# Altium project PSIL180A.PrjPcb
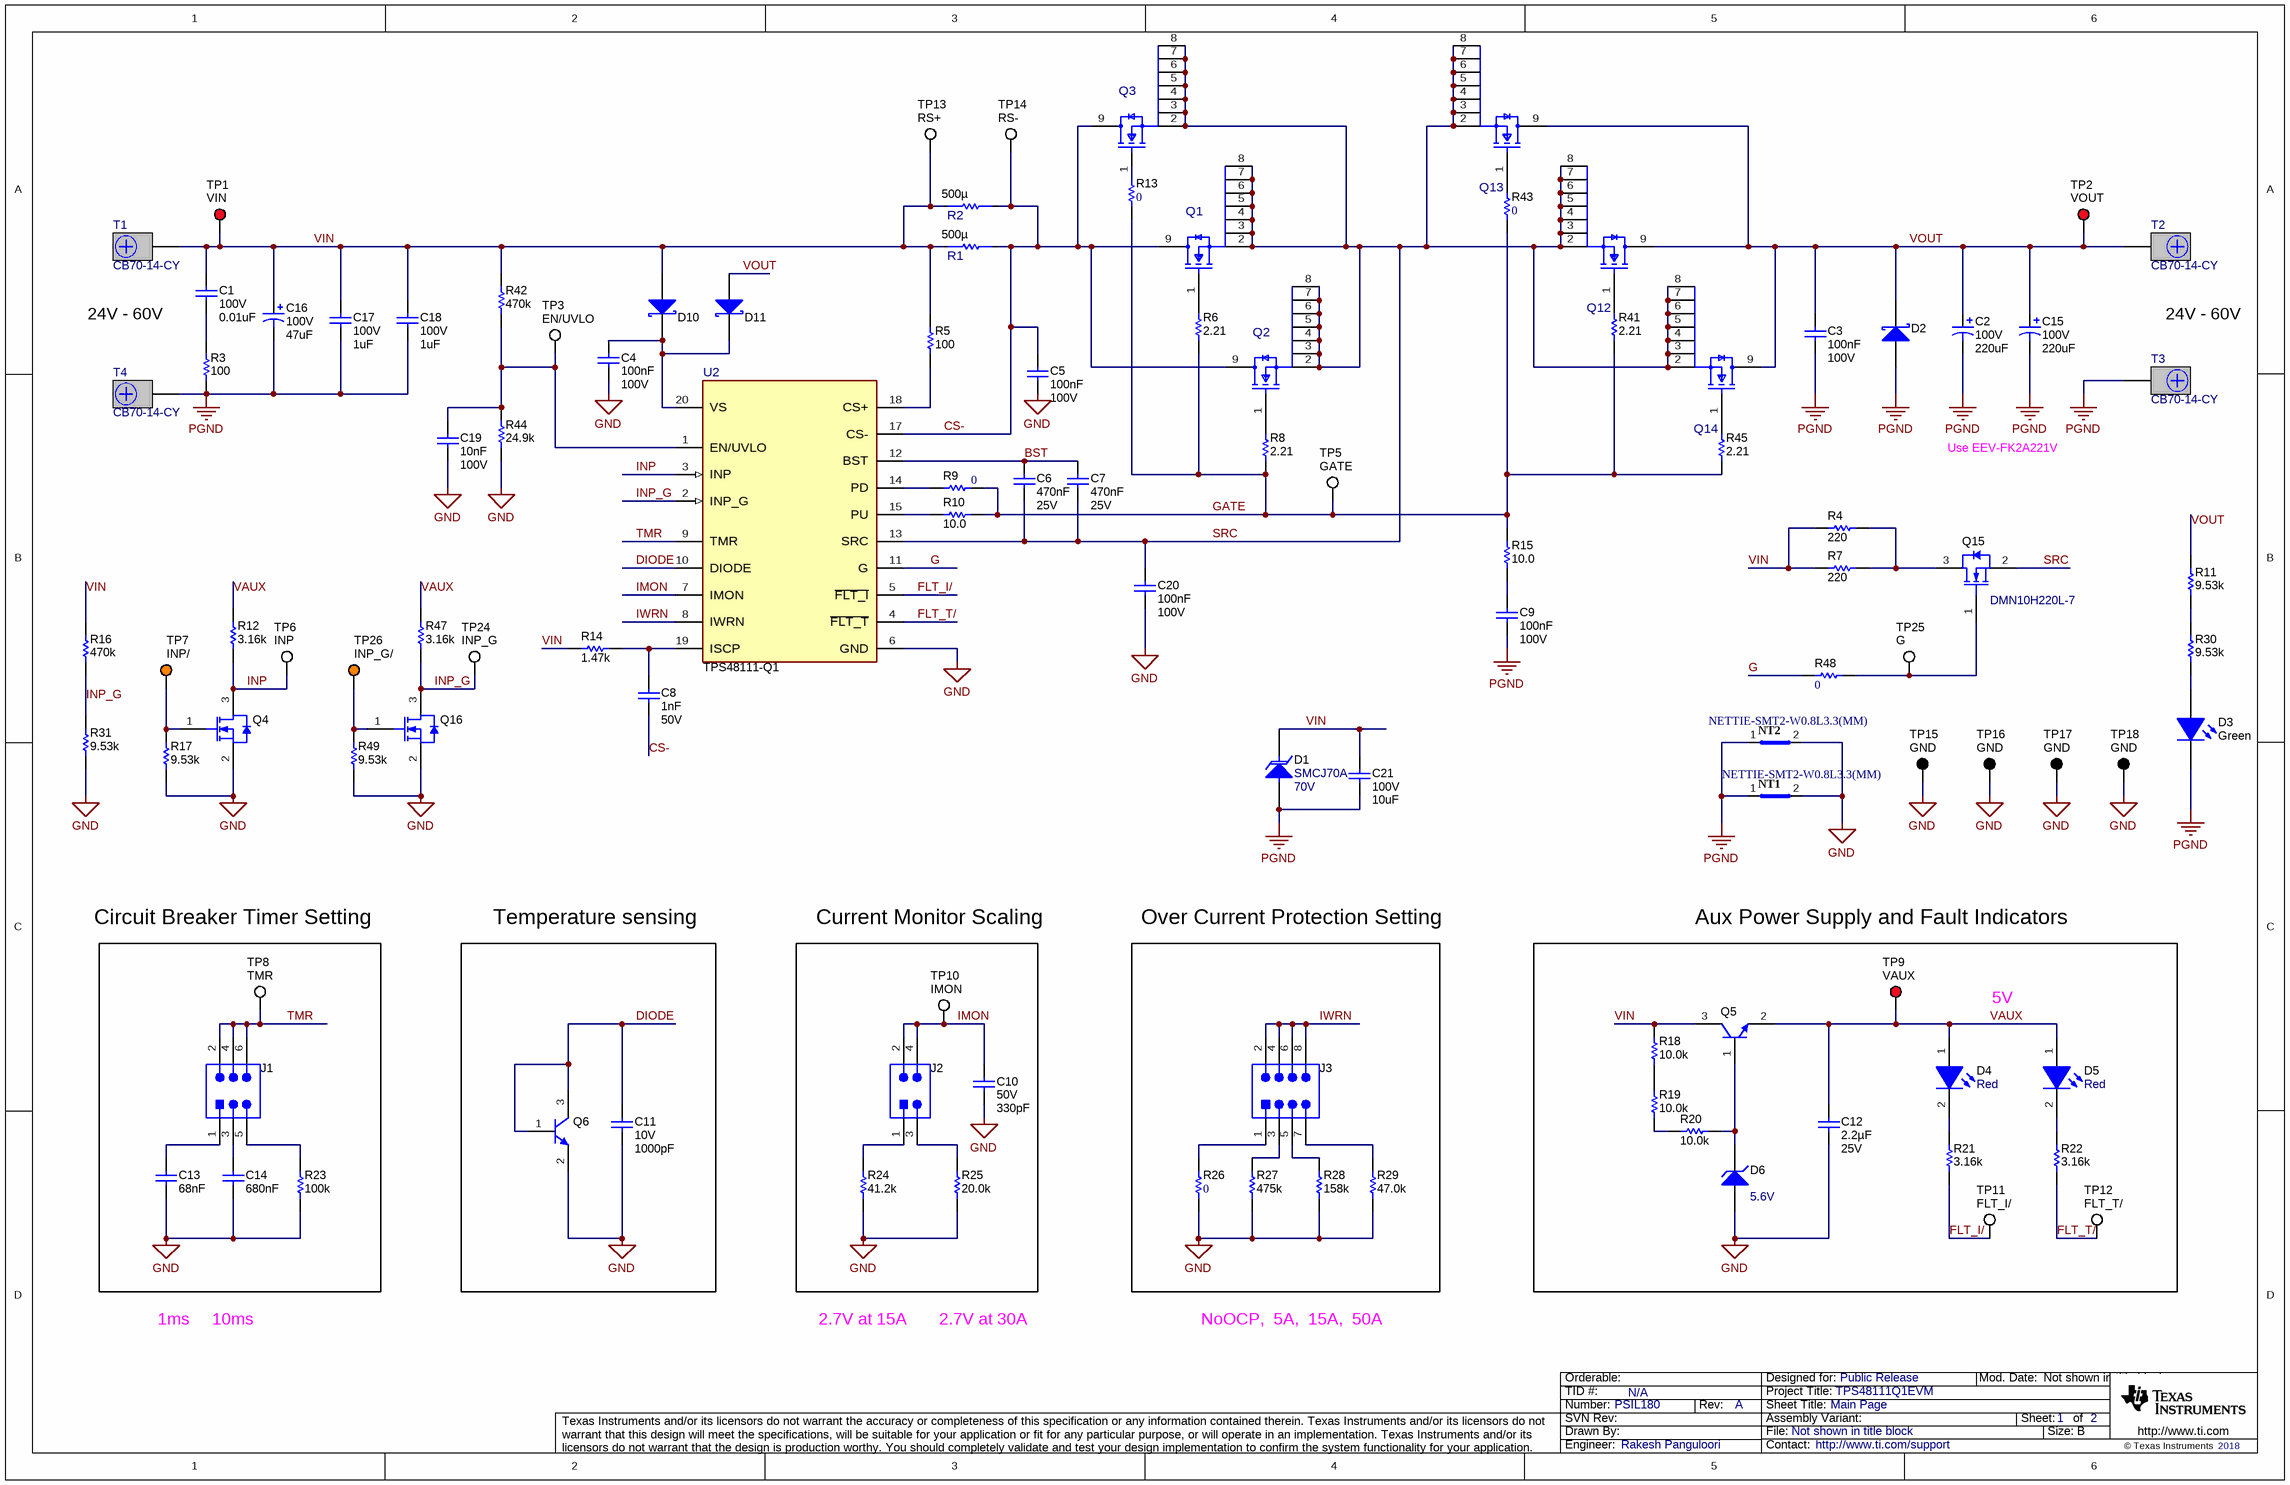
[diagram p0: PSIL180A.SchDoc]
TID: N/A; TechSupport: http://www.ti.com/support; SCH_Rev: A; PRJ_Title: TPS48111Q1EVM; PRJ_Number: PSIL180; PRJ_Engineer: Rakesh Panguloori; PRJ_Customer: Public Release; PCB_Rev: A; CopyrightYear: 2018
2 sheets, 135 parts. Net scope: global (net labels, ports and power ports of the same name join across sheets).
Board file: PSIL180A.PcbDoc
Sheets:
  PSIL180A.SchDoc
  PSIL180A_Hardware.SchDoc

## Sheet PSIL180A.SchDoc: Main Page
size 431 x 279 mm; Date: Not shown in title block; ApprovedBy: Not shown in title block; CheckedBy: Not shown in title block; Author: Not shown in title block; CompanyName: Not shown in title block; Engineer: Not shown in title block; Organization: Not shown in title block; Address1: Not shown in title block; Address2: Not shown in title block; Address3: Not shown in title block; Address4: Not shown in title block; DocumentNumber: 1; Revision: Use project parameter SCH_Rev; SheetNumber: 1; SheetTotal: 2; PageSetup: Record=PageOptions¦CenterHorizontal=True¦CenterVertical=True¦PrintScale=1.00¦XCorrection=1.00¦YCorrection=1.00¦PrintKind=0¦BorderSize=5000000¦LeftOffset=0¦BottomOffset=0¦Orientation=2¦PaperLength=1000¦PaperWidth=1000¦Scale=100¦PaperSource=15¦PrintQuality=600¦MediaType=1¦DitherType=10¦PaperKind=Letter¦PrintScaleMode=1

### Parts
C1  VDC_V: 100V  ValueDisplayed: 0.01uF  [1206]  (hidden comment: 12061C103KAT2A)
C2  VDC_V: 100V  ValueDisplayed: 220uF  [SM_RADIAL_K16]  (hidden comment: EEV-FK2A221M)
C3  Cap_F: 100nF  VDC_V: 100V  [0805_HV]  (hidden comment: CGA4J2X7R2A104K125AA)
C4  Cap_F: 100nF  VDC_V: 100V  [0805_HV]  (hidden comment: CGA4J2X7R2A104K125AA)
C5  Cap_F: 100nF  VDC_V: 100V  [0805_HV]  (hidden comment: CGA4J2X7R2A104K125AA)
C6  Cap_F: 470nF  VDC_V: 25V  [0603]  (hidden comment: CGA3E3X7R1E474K080AB)
C7  Cap_F: 470nF  VDC_V: 25V  [0603]  (hidden comment: CGA3E3X7R1E474K080AB)
C8  Cap_F: 1nF  VDC_V: 50V  [0805_HV]  (hidden comment: C0805C102J5RACTU)
C9  Cap_F: 100nF  VDC_V: 100V  [0805_HV]  (hidden comment: CGA4J2X7R2A104K125AA)
C10  VDC_V: 50V  ValueDisplayed: 330pF  [0402]  (hidden comment: GRM155R71H331KA01D)
C11  VDC_V: 10V  ValueDisplayed: 1000pF  [0402]  (hidden comment: 0402ZC102KAT2A)
C12  Cap_F: 2.2µF  VDC_V: 25V  [0805_HV]  (hidden comment: GCM21BR71E225KA73L)
C13  Cap_F: 68nF  [0805_HV]  (hidden comment: C0805C683K1RACTU)
C14  Cap_F: 680nF  [0805_HV]  (hidden comment: C0805C684K5RACTU)
C15  VDC_V: 100V  ValueDisplayed: 220uF  [SM_RADIAL_K16]  (hidden comment: EEV-FK2A221M)
C16  VDC_V: 100V  ValueDisplayed: 47uF  [SM_RADIAL_H13]  (hidden comment: EEV-FK2A470Q)
C17  VDC_V: 100V  ValueDisplayed: 1uF  [1812_254]  (hidden comment: C4532X7R2A105K230KA)
C18  VDC_V: 100V  ValueDisplayed: 1uF  [1812_254]  (hidden comment: C4532X7R2A105K230KA)
C19  Cap_F: 10nF  VDC_V: 100V  [0805_HV]  (hidden comment: 08051C103JAT2A)
C20  Cap_F: 100nF  VDC_V: 100V  [0805_HV]  (hidden comment: CGA4J2X7R2A104K125AA)
C21  VDC_V: 100V  ValueDisplayed: 10uF  [2220_280]  (hidden comment: 22201C106MAT2A)
D1  SMCJ70A  value 70V  [SMC_265]
D2  SS2H10-E3/5BT  [SMB]  (value not drawn)
D3  value Green  [LTST-C170KGKT_Green]  (hidden comment: LTST-C170KGKT)
D4  value Red  [LED_LTST-C170_Red]  (hidden comment: LTST-C170KRKT)
D5  value Red  [LED_LTST-C170_Red]  (hidden comment: LTST-C170KRKT)
D6  value 5.6V  [SOD-323]  (hidden comment: SZMM3Z5V6ST1G)
D10  BAT46WH,115  [SOD-123F]  (value not drawn)
D11  BAT46WH,115  [SOD-123F]  (value not drawn)
J1  PEC03DAAN  [SULLINS_PEC03DAAN]  (value not drawn)
J2  PEC02DAAN  [Sullins_PEC02DAAN]  (value not drawn)
J3  PEC04DAAN  [CONN_PEC04DAAN]  (value not drawn)
NT1  NETTIE-SMT2-W0.8L3.3(MM)  [NETTIE-SMT2-W0.8L3.3(MM)]  (net tie, no BOM)
NT2  NETTIE-SMT2-W0.8L3.3(MM)  [NETTIE-SMT2-W0.8L3.3(MM)]  (net tie, no BOM)
Q1  IAUS300N08S5N012ATMA1  [FP-IAUS300N08S5N012ATMA1_HSOG-8-MFG]  (value not drawn)
Q2  IAUS300N08S5N012ATMA1  [FP-IAUS300N08S5N012ATMA1_HSOG-8-MFG]  (value not drawn)
Q3  IAUS300N08S5N012ATMA1  [FP-IAUS300N08S5N012ATMA1_HSOG-8-MFG]  (value not drawn)
Q4  2N7002W-7-F  [SOT-323]  (value not drawn)
Q5  PMBT5551,215  [SOT-23]  (value not drawn)
Q6  MMBT3904  [SOT-23]  (value not drawn)
Q12  IAUS300N08S5N012ATMA1  [FP-IAUS300N08S5N012ATMA1_HSOG-8-MFG]  (value not drawn)
Q13  IAUS300N08S5N012ATMA1  [FP-IAUS300N08S5N012ATMA1_HSOG-8-MFG]  (value not drawn)
Q14  IAUS300N08S5N012ATMA1  [FP-IAUS300N08S5N012ATMA1_HSOG-8-MFG]  (value not drawn)
Q15  DMN10H220L-7  [SOT-23]
Q16  2N7002W-7-F  [SOT-323]  (value not drawn)
R1  Res_ohm: 500µ  [FP-WSL3921L5000FEA_3921-MFG]  (hidden comment: WSL3921L5000FEA)
R2  Res_ohm: 500µ  [FP-WSL3921L5000FEA_3921-MFG]  (hidden comment: WSL3921L5000FEA)
R3  ValueDisplayed: 100  [1206]  (hidden comment: CRCW1206100RFKEAHP)
R4  ValueDisplayed: 220  [2512]  (hidden comment: CRCW2512220RFKEG)
R5  ValueDisplayed: 100  [0805_HV]  (hidden comment: CRCW0805100RFKEA)
R6  ValueDisplayed: 2.21  [0603]  (hidden comment: RC0603FR-072R21L)
R7  ValueDisplayed: 220  [2512]  (hidden comment: CRCW2512220RFKEG)
R8  ValueDisplayed: 2.21  [0603]  (hidden comment: RC0603FR-072R21L)
R9  ValueDisplayed: 0  [0603]  (hidden comment: CRCW06030000Z0EA)
R10  ValueDisplayed: 10.0  [0603]  (hidden comment: CRCW060310R0FKEAHP)
R11  ValueDisplayed: 9.53k  [0603]  (hidden comment: RC0603FR-079K53L)
R12  ValueDisplayed: 3.16k  [0603]  (hidden comment: CRCW06033K16FKEA)
R13  ValueDisplayed: 0  [0603]  (hidden comment: CRCW06030000Z0EA)
R14  ValueDisplayed: 1.47k  [0603]  (hidden comment: RT0603BRD071K47L)
R15  ValueDisplayed: 10.0  [0805_HV]  (hidden comment: RC0805FR-0710RL)
R16  ValueDisplayed: 470k  [0603]  (hidden comment: RC0603FR-07470KL)
R17  ValueDisplayed: 9.53k  [0603]  (hidden comment: RC0603FR-079K53L)
R18  ValueDisplayed: 10.0k  [0805_HV]  (hidden comment: ERJ-6ENF1002V)
R19  ValueDisplayed: 10.0k  [0805_HV]  (hidden comment: ERJ-6ENF1002V)
R20  ValueDisplayed: 10.0k  [0805_HV]  (hidden comment: ERJ-6ENF1002V)
R21  ValueDisplayed: 3.16k  [0603]  (hidden comment: CRCW06033K16FKEA)
R22  ValueDisplayed: 3.16k  [0603]  (hidden comment: CRCW06033K16FKEA)
R23  ValueDisplayed: 100k  [0603]  (hidden comment: CRCW0603100KFKEA)
R24  ValueDisplayed: 41.2k  [0603]  (hidden comment: RC0603FR-0741K2L)
R25  ValueDisplayed: 20.0k  [0603]  (hidden comment: RT0603DRE0720KL)
R26  ValueDisplayed: 0  [0603]  (hidden comment: ERJ-3GEY0R00V)
R27  ValueDisplayed: 475k  [0603]  (hidden comment: RC0603FR-07475KL)
R28  ValueDisplayed: 158k  [0603]  (hidden comment: CRCW0603158KFKEA)
R29  ValueDisplayed: 47.0k  [0603]  (hidden comment: CRCW060347K0FKEA)
R30  ValueDisplayed: 9.53k  [0603]  (hidden comment: RC0603FR-079K53L)
R31  ValueDisplayed: 9.53k  [0603]  (hidden comment: RC0603FR-079K53L)
R41  ValueDisplayed: 2.21  [0603]  (hidden comment: RC0603FR-072R21L)
R42  ValueDisplayed: 470k  [0603]  (hidden comment: RC0603FR-07470KL)
R43  ValueDisplayed: 0  [0603]  (hidden comment: CRCW06030000Z0EA)
R44  ValueDisplayed: 24.9k  [0805_HV]  (hidden comment: CRCW080524K9FKEA)
R45  ValueDisplayed: 2.21  [0603]  (hidden comment: RC0603FR-072R21L)
R47  ValueDisplayed: 3.16k  [0603]  (hidden comment: CRCW06033K16FKEA)
R48  ValueDisplayed: 0  [0603]  (hidden comment: ERJ-3GEY0R00V)
R49  ValueDisplayed: 9.53k  [0603]  (hidden comment: RC0603FR-079K53L)
T1  CB70-14-CY  [CB70-14-CY]
T2  CB70-14-CY  [CB70-14-CY]
T3  CB70-14-CY  [CB70-14-CY]
T4  CB70-14-CY  [CB70-14-CY]
TP1  VIN  [Keystone5010]
TP2  VOUT  [Keystone5010]
TP3  EN/UVLO  [Keystone5012]
TP5  GATE  [Keystone5012]
TP6  INP  [Keystone5012]
TP7  INP/  [Keystone5013]
TP8  TMR  [Keystone5012]
TP9  VAUX  [Keystone5010]
TP10  IMON  [Keystone5012]
TP11  FLT_I/  [Keystone5012]
TP12  FLT_T/  [Keystone5012]
TP13  RS+  [Keystone5012]
TP14  RS-  [Keystone5012]
TP15  GND  [Keystone5011]
TP16  GND  [Keystone5011]
TP17  GND  [Keystone5011]
TP18  GND  [Keystone5011]
TP24  INP_G  [Keystone5012]
TP25  G  [Keystone5012]
TP26  INP_G/  [Keystone5013]
U2  PartNumber: TPS48111-Q1  [0-MFG]  (hidden comment: PTPS48111-Q1)

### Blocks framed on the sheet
5V: C12 D4-D6 Q5 R18-R22 TP9 TP11 TP12

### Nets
GND: C4.2 C5.2 C10.2 C11.2 C12.2 C13.2 C14.2 C19.2 C20.2 D6.2(A) NT1.2(Net2) NT2.2(Net2) Q4.2(S) Q6.2(E) Q16.2(S) R17.1 R23.1 R24.1 R25.1 R26.2 R27.1 R28.1 R29.1 R31.1 R44.1 R49.1 TP15.1 TP16.1 TP17.1 TP18.1 U2.6(GND)
PGND: C2.2(-) C3.2 C9.2 C15.2(-) C16.2(-) C17.2 C18.2 C21.2 D1.2(A) D2.2(A) D3.2(K) NT1.1(Net1) NT2.1(Net1) R3.1 T3.1 T4.1
BST: C6.1 C7.1 U2.12(BST)
CS-: C5.1 C8.2 Q1.9(DRAIN) Q2.9(DRAIN) Q3.9(DRAIN) R1.2 R2.2 TP14.1 U2.17(CS-)
DIODE: C11.1 Q6.1(B) Q6.3(C) U2.10(DIODE)
FLT_I/: R21.1 TP11.1 U2.5(~{FLT_I})
FLT_T/: R22.1 TP12.1 U2.4(~{FLT_T})
G: R48.2 U2.11(G)
GATE: R6.1 R8.1 R9.2 R10.2 R13.1 R15.2 R41.1 R43.1 R45.1 TP5.1
IMON: C10.1 J2.2 J2.4 TP10.1 U2.7(IMON)
INP: Q4.3(D) R12.1 TP6.1 U2.3(INP)
INP_G: Q16.3(D) R16.1 R31.2 R47.1 TP24.1 U2.2(INP_G)
IWRN: J3.2 J3.4 J3.6 J3.8 U2.8(IWRN)
SRC: C6.2 C7.2 C20.1 Q1.2(SOURCE) Q1.3(SOURCE) Q1.4(SOURCE) Q1.5(SOURCE) Q1.6(SOURCE) Q1.7(SOURCE) Q1.8(SOURCE) Q2.2(SOURCE) Q2.3(SOURCE) Q2.4(SOURCE) Q2.5(SOURCE) Q2.6(SOURCE) Q2.7(SOURCE) Q2.8(SOURCE) Q3.2(SOURCE) Q3.3(SOURCE) Q3.4(SOURCE) Q3.5(SOURCE) Q3.6(SOURCE) Q3.7(SOURCE) Q3.8(SOURCE) Q12.2(SOURCE) Q12.3(SOURCE) Q12.4(SOURCE) Q12.5(SOURCE) Q12.6(SOURCE) Q12.7(SOURCE) Q12.8(SOURCE) Q13.2(SOURCE) Q13.3(SOURCE) Q13.4(SOURCE) Q13.5(SOURCE) Q13.6(SOURCE) Q13.7(SOURCE) Q13.8(SOURCE) Q14.2(SOURCE) Q14.3(SOURCE) Q14.4(SOURCE) Q14.5(SOURCE) Q14.6(SOURCE) Q14.7(SOURCE) Q14.8(SOURCE) Q15.2(S) U2.13(SRC)
TMR: J1.2 J1.4 J1.6 TP8.1 U2.9(TMR)
VAUX: C12.1 D4.1(A) D5.1(A) Q5.2(E) R12.2 R47.2 TP9.1
VIN: C1.1 C16.1(+) C17.1 C18.1 C21.1 D1.1(K) D10.2(A) Q5.3(C) R1.1 R2.1 R4.1 R5.2 R7.1 R14.1 R16.2 R18.2 R42.2 T1.1 TP1.1 TP13.1
VOUT: C2.1(+) C3.1 C15.1(+) D2.1(K) D11.2(A) Q12.9(DRAIN) Q13.9(DRAIN) Q14.9(DRAIN) R11.2 T2.1 TP2.1
NetC1_2: C1.2 R3.2
NetC4_1: C4.1 D10.1(K) D11.1(K) U2.20(VS)
NetC8_1: C8.1 R14.2 U2.19(ISCP)
NetC9_1: C9.1 R15.1
NetC13_1: C13.1 J1.1
NetC14_1: C14.1 J1.3
NetC19_1: C19.1 R42.1 R44.2 TP3.1 U2.1(EN/UVLO)
NetD3_1: D3.1(A) R30.1
NetD4_2: D4.2(K) R21.2
NetD5_2: D5.2(K) R22.2
NetD6_1: D6.1(K) Q5.1(B) R20.1
NetJ1_5: J1.5 R23.2
NetJ2_1: J2.1 R24.2
NetJ2_3: J2.3 R25.2
NetJ3_1: J3.1 R26.1
NetJ3_3: J3.3 R27.2
NetJ3_5: J3.5 R28.2
NetJ3_7: J3.7 R29.2
NetQ1_1: Q1.1(GATE) R6.2
NetQ2_1: Q2.1(GATE) R8.2
NetQ3_1: Q3.1(GATE) R13.2
NetQ4_1: Q4.1(G) R17.2 TP7.1
NetQ12_1: Q12.1(GATE) R41.2
NetQ13_1: Q13.1(GATE) R43.2
NetQ14_1: Q14.1(GATE) R45.2
NetQ15_1: Q15.1(G) R48.1 TP25.1
NetQ15_3: Q15.3(D) R4.2 R7.2
NetQ16_1: Q16.1(G) R49.2 TP26.1
NetR5_1: R5.1 U2.18(CS+)
NetR9_1: R9.1 U2.14(PD)
NetR10_1: R10.1 U2.15(PU)
NetR11_1: R11.1 R30.2
NetR18_1: R18.1 R19.2
NetR19_1: R19.1 R20.2

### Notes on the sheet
- 24V - 60V
- Use EEV-FK2A221V
- Circuit Breaker Timer Setting
- Temperature sensing
- Current Monitor Scaling
- Over Current Protection Setting
- Aux Power Supply and Fault Indicators
- 1ms     10ms
- 2.7V at 15A
- 2.7V at 30A
- NoOCP,  5A,  15A,  50A

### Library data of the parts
C1 = CMP-0008485-2: CAP, CERM, 0.01 uF, 100 V, +/- 10%, X7R, 1206; Manufacturer: AVX; TaMin_C: -55°C; ESR_ohm: 0.119; Polarized: N; SizeAreaWB_mm2: 10.92; Value1: 0.119 ohm; U/M: EA; Value: 0.01uF; TaMax_C: 125°C; SizeZ_mm: 1.35; SizeX_mm: 3.2; SizeY_mm: 1.6; SizeArea_mm2: 5.12; Cap_F: 10nF; AEC Category: Q200
C2 C15 = CMP-0011223-2: CAP, AL, 220 uF, 100 V, +/- 20%, 0.153 ohm, AEC-Q200 Grade 2, SMD; Manufacturer: Panasonic; TaMin_C: -55°C; ESR_ohm: 0.153; Polarized: Y; SizeAreaWB_mm2: 483; U/M: EA; Value: 220uF; TaMax_C: 105°C; SizeZ_mm: 16.5; SizeX_mm: 21; SizeY_mm: 19; Cap_Case: K16; SizeArea_mm2: 399; CompType: Capacitor; Cap_F: 220µF; IRMS_A: 917mA; AEC Grade: 2; AEC Category: Q200
C3-C5 C9 C20 = CMP-0007969-2: CAP, CERM, 0.1 uF, 100 V, +/- 10%, X7R, AEC-Q200 Grade 1, 0805; Manufacturer: TDK; TaMin_C: -55°C; ESR_ohm: 0.020726; Polarized: N; SizeAreaWB_mm2: 6.75; Value1: 0.020726 ohm; U/M: EA; Value: 0.1uF; TaMax_C: 125°C; SizeZ_mm: 1.45; SizeX_mm: 2; SizeY_mm: 1.25; Cap_Case: 0805; SizeArea_mm2: 2.5; AEC Qualified: Y; IRMS_A: 1.456A; AEC Grade: 1; AEC Category: Q200
C6 C7 = CMP-0007092-5: CAP, CERM, 0.47 uF, 25 V, +/- 10%, X7R, AEC-Q200 Grade 1, 0603; Manufacturer: TDK; TaMin_C: -55°C; Polarized: N; SizeAreaWB_mm2: 4.68; Value1: Unknown; U/M: EA; Value: 0.47uF; TaMax_C: 125°C; SizeZ_mm: 1; SizeX_mm: 1.6; SizeY_mm: 0.8; SizeArea_mm2: 1.28; AEC Qualified: Y; AEC Category: Q200
C8 = CMP-0007711-2: CAP, CERM, 1000 pF, 50 V, +/- 5%, X7R, 0805; Manufacturer: Kemet; TaMin_C: -55°C; ESR_ohm: 0.384; Polarized: N; SizeAreaWB_mm2: 6.75; Value1: 0.384 ohm; U/M: EA; Value: 1000pF; TaMax_C: 125°C; SizeZ_mm: 1.45; SizeX_mm: 2; SizeY_mm: 1.25; Cap_Case: 0805; SizeArea_mm2: 2.5; IRMS_A: 214mA; AEC Category: Q200
C10 = CMP-0006687-2: CAP, CERM, 330 pF, 50 V, +/- 10%, X7R, 0402; Manufacturer: MuRata; TaMin_C: -55°C; Polarized: N; SizeAreaWB_mm2: 3; Value1: Unknown; U/M: EA; Value: 330pF; TaMax_C: 125°C; SizeZ_mm: 0.6; SizeX_mm: 1; SizeY_mm: 0.5; AEC Category: Q200
C11 = CMP-0860545-1: CAP, CERM, 1000 pF, 10 V,+/- 10%, X7R, 0402; Manufacturer: AVX; Cap_F: 1nF; SizeArea_mm2: 0.5; SizeAreaWB_mm2: 3; Polarized: N; TaMin_C: -55°C; AEC Category: Q200; SizeZ_mm: 0.6; U/M: EA; Value: 1000pF; TaMax_C: 125°C; SizeX_mm: 1
C12 = CMP-0083622-1: CAP, CERM, 2.2 µF, 25 V,+/- 10%, X7R, AEC-Q200 Grade 1, 0805; Manufacturer: MuRata; TaMin_C: -55°C; Polarized: N; SizeAreaWB_mm2: 6.75; U/M: EA; Value: 2.2uF; TaMax_C: 125°C; SizeZ_mm: 1.45; SizeX_mm: 2; SizeY_mm: 1.25; Cap_Case: 0805; SizeArea_mm2: 2.5; AEC Qualified: Y; AEC Grade: 1; AEC Category: Q200
C13 = CMP-0007813-2: CAP, CERM, 0.068 uF, 100 V, +/- 10%, X7R, 0805; Manufacturer: Kemet; TaMin_C: -55°C; ESR_ohm: 0.078; Polarized: N; SizeAreaWB_mm2: 6.75; Value1: 0.078 ohm; U/M: EA; TaMax_C: 125°C; SizeZ_mm: 1.45; SizeX_mm: 2; SizeY_mm: 1.25; Cap_Case: 0805; Value2: 100V; SizeArea_mm2: 2.5; IRMS_A: 1.28A; AEC Category: Q200
C14 = CMP-0007814-2: CAP, CERM, 0.68 uF, 50 V, +/- 10%, X7R, 0805; Manufacturer: Kemet; TaMin_C: -55°C; Polarized: N; SizeAreaWB_mm2: 6.75; Value1: Unknown; U/M: EA; Value: 0.68uF; TaMax_C: 125°C; SizeZ_mm: 1.45; SizeX_mm: 2; SizeY_mm: 1.25; Cap_Case: 0805; Value2: 50V; SizeArea_mm2: 2.5; AEC Category: Q200
C16 = CMP-0011225-2: CAP, AL, 47 uF, 100 V, +/- 20%, 0.32 ohm, AEC-Q200 Grade 2, SMD; Manufacturer: Panasonic; TaMin_C: -55°C; ESR_ohm: 0.32; Polarized: Y; SizeAreaWB_mm2: 263.5; U/M: EA; Value: 47uF; TaMax_C: 105°C; SizeZ_mm: 13.5; SizeX_mm: 15; Cap_Case: H13; SizeArea_mm2: 202.5; CompType: Capacitor; Cap_F: 47µF; IRMS_A: 500mA; AEC Grade: 2; AEC Category: Q200
C17 C18 = CMP-0009354-2: CAP, CERM, 1 uF, 100 V, +/- 10%, X7R, 1812; Manufacturer: TDK; TaMin_C: -55°C; ESR_ohm: 5.865m; Polarized: N; SizeAreaWB_mm2: 23.1; Value1: 0.005865 ohm; U/M: EA; Value: 1uF; TaMax_C: 125°C; SizeZ_mm: 2.54; SizeX_mm: 4.5; SizeY_mm: 3.2; SizeArea_mm2: 14.4; Cap_F: 1µF; IRMS_A: 3.17165A; AEC Category: Q200
C19 = CMP-0007542-2: CAP, CERM, 0.01 uF, 100 V, +/- 5%, X7R, 0805; Manufacturer: AVX; TaMin_C: -55°C; ESR_ohm: 0.078; Polarized: N; SizeAreaWB_mm2: 6.75; Value1: 0.078 ohm; U/M: EA; Value: 0.01uF; TaMax_C: 125°C; SizeZ_mm: 1.45; SizeX_mm: 2; SizeY_mm: 1.25; Cap_Case: 0805; SizeArea_mm2: 2.5; AEC Category: Q200
C21 = CMP-0009304-2: CAP, CERM, 10 uF, 100 V, +/- 20%, X7R, 2220; Manufacturer: AVX; TaMin_C: -55°C; Polarized: N; SizeAreaWB_mm2: 53.9; Value1: Unknown; U/M: EA; Value: 10uF; TaMax_C: 125°C; SizeZ_mm: 2.8; SizeX_mm: 5.7; SizeY_mm: 5; Cap_Case: 2220; SizeArea_mm2: 28.5; Cap_F: 10µF; AEC Category: Q200
D1 = CMP-0005734-3: Diode, TVS, Uni, 70 V, 113 Vc, SMC; Manufacturer: Littelfuse; AEC Qualified: N; SizeAreaWB_mm2: 78.5757; SizeX_mm: 7.94; SizeArea_mm2: 46.8857; Ipp: 13.3A; RJA_CperW: 75; SizeY_mm: 5.905; Vbr_Max: 86V; SizeZ_mm: 2.62; Vbr_Min: 77.8V; Vc: 113V; Ppk: 1.5kW; AEC Category: Q101; Value1: 1500W
D2 = CMP-0028987-2: Diode, Schottky, 100 V, 2 A, SMB; Manufacturer: Vishay-Semiconductor; Vf_V: 790mV; AEC Qualified: N; SizeArea_mm2: 21.336; Value: 100V; SizeX_mm: 5.6; Value1: 2A; Value2: 0.79V; SizeZ_mm: 2.6; SizeAreaWB_mm2: 44.156; AEC Category: Q101; TJmax_C: 175°C; SizeY_mm: 3.81
D3 = CMP-0002888-1: LED, Green, SMD; Manufacturer: Lite-On; Type: AlInGaP; Vf_V: 2V; Io_A: 20mA; Value1: W; U/M: EA
D4 D5 = CMP-0002829-3: LED, Red, SMD; Manufacturer: Lite-On; SizeZ_mm: 1.2; Value1: W; SizeY_mm: 1.25; Value2: 2V; SizeArea_mm2: 2.5; SizeX_mm: 2; SizeAreaWB_mm2: 6.75; Io_A: 20mA; Type: AlInGaP
D6 = CMP-0085742-1: Diode, Zener, 5.6 V, 300 mW, AEC-Q101, SOD-323; Manufacturer: ON Semiconductor; SizeAreaWB_mm2: 8.695; SizeY_mm: 1.35; SizeZ_mm: 1; AEC Qualified: Y; SizeArea_mm2: 3.645; Value1: 0.3W; Power_W: 300mW; RJA_CperW: 416; AEC Category: Q101; SizeX_mm: 2.7
D10 D11 = CMP-0028632-2: Diode, Schottky, 100 V, 0.25 A, SOD-123F; Manufacturer: Nexperia; AEC Category: Q101; Value2: 0.85V; Value: 100V; Green_REACh: Incomplete; Value1: 0.25A; SizeY_mm: 1.6; SizeAreaWB_mm2: 11.7; TJmax_C: 150°C; Green_Lifecycle: Not Set; SizeZ_mm: 1.1; Io_A: 250mA; Vf_V: 850mV; SizeArea_mm2: 5.6; SizeX_mm: 3.5
J1 = CMP-0054552-1: Header, 100mil, 3x2, Tin, TH; Manufacturer: Sullins Connector Solutions; CNHeader: TRUE; Current_A: 3A; Green_Lifecycle: Not Set; Shrouded: N; Gender: Male; Green_REACh: Incomplete; Voltage_V: 1.8kV; Row_Count: 2; RowSpacing_mm: 2.54; CT: FALSE; Cert_UL: Y
J2 = CMP-0054558-1: Header, 100mil, 2x2, Tin, TH; Manufacturer: Sullins Connector Solutions; CNHeader: TRUE; Green_Lifecycle: Not Set; Green_REACh: Incomplete; CT: FALSE
J3 = CMP-0054542-1: Header, 100mil, 4x2, Tin, TH; Manufacturer: Sullins Connector Solutions; CNHeader: TRUE; Current_A: 3A; Green_Lifecycle: Not Set; Shrouded: N; Gender: Male; Green_REACh: Incomplete; Voltage_V: 1.8kV; Row_Count: 2; RowSpacing_mm: 2.54; CT: FALSE; Cert_UL: Y
NT1 NT2 = CMP-0494-00001-2: Net-Tie, Surface Mount, 3.3 mm x 0.8 mm, 2 Pads (2.0 mm x 0.8 mm); Manufacturer: No Vendor
Q1-Q3 Q12-Q14 = CMP-0089282-1: N-Channel 80V 300A (Tc) 375W (Tc) Surface Mount PG-HSOG-8-1; Manufacturer: Infineon; Standoff Height: 0mm; AEC Grade: Grade 0; Turn On Delay Time: 31ns; TJmax_C: +175°C; Pulse Drain Current: 1200A; Input Capacitace At Vds: 12500pF @ 40V; Reverse Recovery Charge: 177nC; Rdson45_ohm: 1m; ChMode: False; VdsMax_V: 1.2V; Turn Off Delay Time: 69ns; Number Of N Channels: 1; Threshold Vgs Min: 2.2V; Threshold Vgs Max: 3.8V; QgTyp_nC: 178nC @ 10V; Vgs_V: 20V; Reverse Recovery Time: 86ns; AEC Qualified: Yes; Typ Forward Diode Voltage: 0.9V; SizeZ_mm: 2.4mm
Q4 Q16 = CMP-0000776-1: MOSFET, N-CH, 60 V, 0.115 A, SOT-323; Alternate Manufacturer: None; Manufacturer: Diodes Inc.; SizeZ_mm: 1.1; ChType: N; Value1: 7; VdsMax_V: 60V; SizeX_mm: 2.2; Vgs_V: 20V; Value: 60V; Rdson45_ohm: 7.5; SizeArea_mm2: 4.84; AEC Category: Q101; IdsMax_A: 115mA; SizeAreaWB_mm2: 10.24; U/M: EA
Q5 = CMP-0750056-1: Transistor, NPN, 160 V, 0.3 A, SOT-23; Manufacturer: Nexperia; TaMax_C: 150°C; IcRated_A: 300mA; SizeX_mm: 2.5; NPN: 1; AEC Qualified: N; TaMin_C: -65°C; PNP: 0; SizeArea_mm2: 7.5; SizeY_mm: 3; SizeAreaWB_mm2: 14; CompType: BJT; SizeZ_mm: 1.1; Vcesat1_V: 150mV; Value: 160 V; Value2: 250; Vceo_V: 160V; AEC Category: Q101; Value1: 0.3 A
Q6 = CMP-0000386-2: Transistor, NPN, 40 V, 0.2 A, SOT-23; Manufacturer: Fairchild Semiconductor; TaMax_C: 150°C; Value2: 300; Value1: 0.2 A; Vcesat1_V: 200mV; SizeX_mm: 2.5; SizeY_mm: 3; TaMin_C: -55°C; IcRated_A: 200mA; CompType: BJT; SizeZ_mm: 1.1; Value: 40 V; SizeArea_mm2: 7.5; NPN: 1; Vceo_V: 40V; PNP: 0; AEC Category: Q101; SizeAreaWB_mm2: 14; U/M: EA
Q15 = CMP-0000971-2: MOSFET, N-CH, 100 V, 1.4 A, SOT-23; Alternate Manufacturer: None; Manufacturer: Diodes Inc.; SizeZ_mm: 1.1; ChType: N; Value2: 4.1 nC; Value1: 0.2; VdsMax_V: 100V; SizeX_mm: 2.5; SizeY_mm: 3; Vgs_V: 16V; Value: 100V; Rdson45_ohm: 0.25; SizeArea_mm2: 7.5; AEC Category: Q101; IdsMax_A: 1.4A; SizeAreaWB_mm2: 14; U/M: EA; QgTyp_nC: 4.1
R1 R2 = CMP-0092921-1: Res Metal Strip 3921 0.0005 Ohm 1% 3W ±175ppm/°C Molded SMD SMD Embossed Plastic T/R; Manufacturer: Vishay Dale; Value: 500µ; TempCo: 150ppm/°C; SizeZ_mm: 0.05inch; AEC Qualified: Yes; AEC Grade: Grade 0
R3 = CMP-0016570-3: RES, 100, 1%, 0.5 W, AEC-Q200 Grade 0, 1206; Manufacturer: Vishay-Dale; Power_W: 500mW; TempCo: 100 ppm/C; Value_Code: 100R; Value: 100; EIA_Code: E96; SizeX_mm: 3.2; SizeY_mm: 1.6; SizeZ_mm: 1.35; Value2: 0.5W; SizeArea_mm2: 5.12; AEC Qualified: Y; AEC Grade: 0; AEC Category: Q200
R4 R7 = CMP-0015538-3: RES, 220, 1%, 1 W, AEC-Q200 Grade 0, 2512; Manufacturer: Vishay-Dale; Power_W: 1W; TempCo: 100 ppm/C; Value_Code: 220R; Value: 220; SizeX_mm: 6.3; SizeY_mm: 3.2; SizeZ_mm: 0.71; SizeArea_mm2: 20.16; AEC Qualified: Y; VDC_V: 500V; AEC Grade: 0; AEC Category: Q200
R5 = CMP-0020835-3: RES, 100, 1%, 0.125 W, AEC-Q200 Grade 0, 0805; Manufacturer: Vishay-Dale; Power_W: 125mW; TempCo: 100 ppm/C; Value_Code: 100R; Value: 100; EIA_Code: E96; SizeX_mm: 2; SizeY_mm: 1.25; SizeZ_mm: 1.45; Value2: 0.125W; SizeArea_mm2: 2.5; AEC Qualified: Y; VDC_V: 150V; AEC Category: Q200; AEC Grade: 0
R6 R8 R41 R45 = CMP-0023007-4: RES, 2.21, 1%, 0.1 W, 0603; Manufacturer: Yageo; Power_W: 100mW; TempCo: 200 ppm/C; Value_Code: 2R21; Value: 2.21; EIA_Code: E96; SizeX_mm: 1.6; SizeY_mm: 0.8; SizeZ_mm: 1; Value2: 0.1W; SizeArea_mm2: 1.28; AEC Qualified: N; VDC_V: 75V; AEC Category: Q200; SizeAreaWB_mm2: 4.68
R9 R13 R43 = CMP-0025697-4: RES, 0, 5%, 0.1 W, AEC-Q200 Grade 0, 0603; Manufacturer: Vishay-Dale; Power_W: 100mW; TempCo: 200 ppm/C; Value_Code: 0000; Value: 0; EIA_Code: E24; SizeX_mm: 1.6; SizeY_mm: 0.8; SizeZ_mm: 1; Value2: 0.1W; SizeArea_mm2: 1.28; CompType: Resistor; AEC Qualified: Y; VDC_V: 75V; AEC Category: Q200
R10 = CMP-0022004-4: RES, 10.0, 1%, 0.25 W, AEC-Q200 Grade 0, 0603; Manufacturer: Vishay-Dale; Power_W: 250mW; TempCo: 100 ppm/C; Value_Code: 10R0; Value: 10.0; EIA_Code: E96; Res_ohm: 10; SizeX_mm: 1.6; SizeY_mm: 0.8; SizeZ_mm: 1; Value2: 0.25W; SizeArea_mm2: 1.28; AEC Qualified: Y; VDC_V: 75V; AEC Category: Q200; AEC Grade: 0
R11 R17 R30 R31 R49 = CMP-0023335-5: RES, 9.53 k, 1%, 0.1 W, 0603; Manufacturer: Yageo; Power_W: 100mW; TempCo: 100 ppm/C; Value_Code: 9k53; Value: 9.53k; EIA_Code: E96; SizeX_mm: 1.6; SizeY_mm: 0.8; SizeZ_mm: 1; Value2: 0.1W; SizeArea_mm2: 1.28; AEC Qualified: N; VDC_V: 75V; AEC Category: Q200; SizeAreaWB_mm2: 4.68
R12 R21 R22 R47 = CMP-0022373-4: RES, 3.16 k, 1%, 0.1 W, AEC-Q200 Grade 0, 0603; Manufacturer: Vishay-Dale; Power_W: 100mW; TempCo: 100 ppm/C; Value_Code: 3k16; Value: 3.16k; EIA_Code: E96; SizeX_mm: 1.6; SizeY_mm: 0.8; SizeZ_mm: 1; Value2: 0.1W; SizeArea_mm2: 1.28; AEC Qualified: Y; VDC_V: 75V; AEC Category: Q200; AEC Grade: 0
R14 = CMP-0023892-3: RES, 1.47 k, 0.1%, 0.1 W, 0603; Manufacturer: Yageo America; Power_W: 100mW; TempCo: 25 ppm/C; Value_Code: 1k47; U/M: EA; Value: 1.47k; EIA_Code: E192; SizeX_mm: 1.6; SizeY_mm: 0.8; SizeZ_mm: 1; Value2: 0.1W; SizeArea_mm2: 1.28; VDC_V: 75V; AEC Category: Q200
R15 = CMP-0021863-2: RES, 10.0, 1%, 0.125 W, 0805; Manufacturer: Yageo America; Power_W: 125mW; TempCo: 200 ppm/C; Value_Code: 10R0; U/M: EA; Value: 10.0; EIA_Code: E96; Res_ohm: 10; SizeX_mm: 2; SizeY_mm: 1.25; SizeZ_mm: 1.45; Value2: 0.125W; SizeArea_mm2: 2.5; VDC_V: 150V; AEC Category: Q200
R16 R42 = CMP-0023128-4: RES, 470 k, 1%, 0.1 W, 0603; Manufacturer: Yageo; Power_W: 100mW; TempCo: 100 ppm/C; Value: 470k; SizeX_mm: 1.6; SizeY_mm: 0.8; SizeZ_mm: 1; Value2: 0.1W; SizeArea_mm2: 1.28; AEC Qualified: N; VDC_V: 75V; AEC Category: Q200; SizeAreaWB_mm2: 4.68
R18-R20 = CMP-0021520-3: RES, 10.0 k, 1%, 0.125 W, AEC-Q200 Grade 0, 0805; Manufacturer: Panasonic; Power_W: 125mW; TempCo: 100 ppm/C; Value_Code: 10k0; Value: 10.0k; EIA_Code: E96; Res_ohm: 10k; SizeX_mm: 2; SizeY_mm: 1.25; SizeZ_mm: 1.45; Value2: 0.125W; SizeArea_mm2: 2.5; AEC Qualified: Y; AEC Category: Q200; AEC Grade: 0; SizeAreaWB_mm2: 6.75
R23 = CMP-0021990-4: RES, 100 k, 1%, 0.1 W, AEC-Q200 Grade 0, 0603; Manufacturer: Vishay-Dale; Power_W: 100mW; TempCo: 100 ppm/C; Value: 100k; EIA_Code: E96; SizeX_mm: 1.6; SizeY_mm: 0.8; SizeZ_mm: 1; Value2: 0.1W; SizeArea_mm2: 1.28; AEC Qualified: Y; VDC_V: 75V; AEC Category: Q200; AEC Grade: 0
R24 = CMP-0023102-5: RES, 41.2 k, 1%, 0.1 W, 0603; Manufacturer: Yageo; Power_W: 100mW; TempCo: 100 ppm/C; Value_Code: 41k2; Value: 41.2k; EIA_Code: E96; SizeX_mm: 1.6; SizeY_mm: 0.8; SizeZ_mm: 1; Value2: 0.1W; SizeArea_mm2: 1.28; AEC Qualified: N; VDC_V: 75V; AEC Category: Q200; SizeAreaWB_mm2: 4.68
R25 = CMP-0024922-3: RES, 20.0 k, 0.5%, 0.1 W, 0603; Manufacturer: Yageo America; Power_W: 100mW; TempCo: 50 ppm/C; Value_Code: 20k0; U/M: EA; Value: 20.0k; EIA_Code: E192; Res_ohm: 20k; SizeX_mm: 1.6; SizeY_mm: 0.8; SizeZ_mm: 1; Value2: 0.1W; SizeArea_mm2: 1.28; VDC_V: 75V; AEC Category: Q200
R26 R48 = CMP-0025874-2: RES, 0, 5%, 0.1 W, 0603; Manufacturer: Panasonic; Power_W: 100mW; TempCo: 600 ppm/C; Value_Code: 0000; U/M: EA; Value: 0; EIA_Code: E24; SizeX_mm: 1.6; SizeY_mm: 0.8; SizeZ_mm: 1; Value2: 0.1W; SizeArea_mm2: 1.28; VDC_V: 50V; AEC Category: Q200
R27 = CMP-0023130-4: RES, 475 k, 1%, 0.1 W, 0603; Manufacturer: Yageo; Power_W: 100mW; TempCo: 100 ppm/C; Value: 475k; EIA_Code: E96; SizeX_mm: 1.6; SizeY_mm: 0.8; SizeZ_mm: 1; Value2: 0.1W; SizeArea_mm2: 1.28; AEC Qualified: N; VDC_V: 75V; AEC Category: Q200; SizeAreaWB_mm2: 4.68
R28 = CMP-0022064-4: RES, 158 k, 1%, 0.1 W, AEC-Q200 Grade 0, 0603; Manufacturer: Vishay-Dale; Power_W: 100mW; TempCo: 100 ppm/C; Value: 158k; EIA_Code: E96; SizeX_mm: 1.6; SizeY_mm: 0.8; SizeZ_mm: 1; Value2: 0.1W; SizeArea_mm2: 1.28; AEC Qualified: Y; VDC_V: 75V; AEC Category: Q200; AEC Grade: 0
R29 = CMP-0022438-4: RES, 47.0 k, 1%, 0.1 W, AEC-Q200 Grade 0, 0603; Manufacturer: Vishay-Dale; Power_W: 100mW; TempCo: 100 ppm/C; Value_Code: 47k0; Value: 47.0k; Res_ohm: 47k; SizeX_mm: 1.6; SizeY_mm: 0.8; SizeZ_mm: 1; Value2: 0.1W; SizeArea_mm2: 1.28; AEC Qualified: Y; VDC_V: 75V; AEC Grade: 0; AEC Category: Q200
R44 = CMP-0021075-3: RES, 24.9 k, 1%, 0.125 W, AEC-Q200 Grade 0, 0805; Manufacturer: Vishay-Dale; Power_W: 125mW; TempCo: 100 ppm/C; Value_Code: 24k9; Value: 24.9k; EIA_Code: E96; SizeX_mm: 2; SizeY_mm: 1.25; SizeZ_mm: 1.45; Value2: 0.125W; SizeArea_mm2: 2.5; AEC Qualified: Y; VDC_V: 150V; AEC Category: Q200; AEC Grade: 0
T1-T4 = CMP-0055443-2: Terminal 90A Lug; Manufacturer: Panduit; Green_Lifecycle: Not Set; Cert_CULUS: Y; Green_REACh: Incomplete; Voltage_V: 600V; CompType: Screw Terminal; ContactFinish: Copper
TP1 TP2 TP9 = CMP-0055147-1: Test Point, Multipurpose, Red, TH; Manufacturer: Keystone; PartNumber: 5010; CNHeader: FALSE; Green_Lifecycle: Active; Green_REACh: Passed; ContactFinish: Silver; CT: TRUE
TP3 TP5 TP6 TP8 TP10-TP14 TP24 TP25 = CMP-0055149-1: Test Point, Multipurpose, White, TH; Manufacturer: Keystone; PartNumber: 5012; CNHeader: FALSE; Green_Lifecycle: Active; Green_REACh: Passed; ContactFinish: Silver; CT: TRUE
TP7 TP26 = CMP-0055150-1: Test Point, Multipurpose, Orange, TH; Manufacturer: Keystone; PartNumber: 5013; CNHeader: FALSE; Green_Lifecycle: Active; Green_REACh: Passed; ContactFinish: Silver; CT: TRUE
TP15-TP18 = CMP-0055148-1: Test Point, Multipurpose, Black, TH; Manufacturer: Keystone; PartNumber: 5011; CNHeader: FALSE; Green_Lifecycle: Active; Green_REACh: Passed; ContactFinish: Silver; CT: TRUE
U2 = CMP-0092088-1: 100V Smart High Side controller with Protection and Diagnostics; Manufacturer: Texas Instruments; SizeZ_mm: 1.1mm; Max Supply Voltage: 80V; Standoff Height: 0.05mm; Number Of Outputs: 1; Nominal Supply Current: 1uA; AEC Qualified: Yes; Min Supply Voltage: 3.5V

## Sheet PSIL180A_Hardware.SchDoc
size 431 x 279 mm; Date: Not shown in title block; ApprovedBy: Not shown in title block; CheckedBy: Not shown in title block; Author: Not shown in title block; CompanyName: Not shown in title block; Engineer: Not shown in title block; Organization: Not shown in title block; Address1: Not shown in title block; Address2: Not shown in title block; Address3: Not shown in title block; Address4: Not shown in title block; DocumentNumber: 1; Revision: Use project parameter SCH_Rev; SheetNumber: 2; SheetTotal: 2; PageSetup: Record=PageOptions¦CenterHorizontal=True¦CenterVertical=True¦PrintScale=1.00¦XCorrection=1.00¦YCorrection=1.00¦PrintKind=0¦BorderSize=5000000¦LeftOffset=0¦BottomOffset=0¦Orientation=2¦PaperLength=1000¦PaperWidth=1000¦Scale=100¦PaperSource=15¦PrintQuality=600¦MediaType=1¦DitherType=10¦PaperKind=Letter¦PrintScaleMode=1
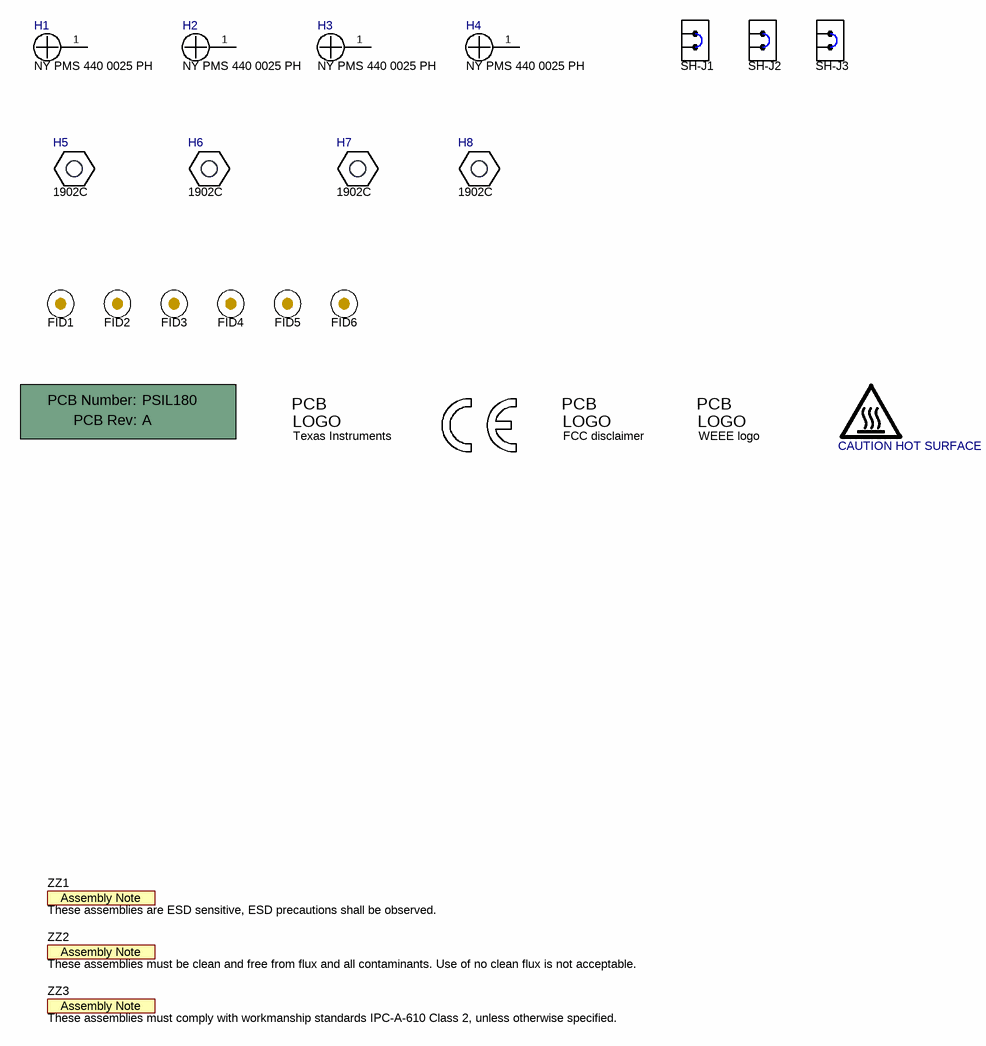
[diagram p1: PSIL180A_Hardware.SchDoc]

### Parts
!PCB1  Printed Circuit Board  (value not drawn)  (mechanical)
FID1  Fiducial  [Fiducial10-20]  (value not drawn)
FID2  Fiducial  [Fiducial10-20]  (value not drawn)
FID3  Fiducial  [Fiducial10-20]  (value not drawn)
FID4  Fiducial  [Fiducial10-20]  (value not drawn)
FID5  Fiducial  [Fiducial10-20]  (value not drawn)
FID6  Fiducial  [Fiducial10-20]  (value not drawn)
H1  NY PMS 440 0025 PH  [NY PMS 440 0025 PH]
H2  NY PMS 440 0025 PH  [NY PMS 440 0025 PH]
H3  NY PMS 440 0025 PH  [NY PMS 440 0025 PH]
H4  NY PMS 440 0025 PH  [NY PMS 440 0025 PH]
H5  1902C  [Keystone_1902C]
H6  1902C  [Keystone_1902C]
H7  1902C  [Keystone_1902C]
H8  1902C  [Keystone_1902C]
Logo1  Texas Instruments  [TI_Stacked_Overlay_Small]  (no BOM)
Logo2  FCC disclaimer  [FCC_disclaimer]  (no BOM)
Logo3  WEEE logo  [WEEE_Minimum]  (no BOM)
LOGO4  CE Mark  [CE_Mark_5mm]  (value not drawn)  (no BOM)
LOGO6  CAUTION HOT SURFACE  [IEC_HotSurface_Medium]  (no BOM)
SH-J1  Shunt  [SPC02SYAN]  (value not drawn)
SH-J2  Shunt  [SPC02SYAN]  (value not drawn)
SH-J3  Shunt  [SPC02SYAN]  (value not drawn)
ZZ1  These assemblies are ESD sensitive, ESD precautions shall be observed.  [AssemblyNote]  (no BOM)
ZZ2  These assemblies must be clean and free from flux and all contaminants. Use of no clean flux is not acceptable.  [AssemblyNote]  (no BOM)
ZZ3  These assemblies must comply with workmanship standards IPC-A-610 Class 2, unless otherwise specified.  [AssemblyNote]  (no BOM)

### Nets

Not connected (* = marked no-connect by the designer): H1 1; H2 1; H3 1; H4 1

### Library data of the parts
!PCB1 = CMP-0003618-2: Manufacturer: Any; PartNumber: PSIL180
FID1-FID6 = CMP-0077181-1: Fiducial mark.  There is nothing to buy or mount.
H1-H4 = CMP-0003617-1: Machine Screw, Round, #4-40 x 1/4, Nylon, Philips panhead; Manufacturer: B&F Fastener Supply; CompType: Hardware
H5-H8 = CMP-0003610-1: Manufacturer: Keystone; CompType: Hardware
Logo1 = CMP-0074838-1: Texas Instrument Corporate Signature; SymbolCreator: a0412235; Lib Reference: TI_Logo; Library Reference: Logo
Logo2 = CMP-0074847-1: FCC_disclaimer; Library Reference: Logo
Logo3 = CMP-0074769-1
LOGO4 = CMP-0074844-1: SymbolCreator: a0412235
LOGO6 = CMP-0074837-1: IEC 61010-1 Hot Surface Warning; SymbolCreator: a0412235
SH-J1-SH-J3 = CMP-0003642-1: Shunt, 100mil, Flash Gold, Black; Manufacturer: Sullins Connector Solutions; Value: 1x2; Note: You can "mate" this to a header by matching the designator.  i.e. use SH-J3 for header J3
ZZ1 = CMP-0077236-1
ZZ2 = CMP-0077237-1
ZZ3 = CMP-0077238-1

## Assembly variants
001: not fitted C1 C5 C7 C9 C10 C19 C20 D1 FID1 FID2 FID3 FID4 FID5 FID6 Q3 Q13 R2 R3 R13 R15 R16 R31 R43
